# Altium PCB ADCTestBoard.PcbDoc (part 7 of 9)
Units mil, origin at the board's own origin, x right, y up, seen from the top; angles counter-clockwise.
Board outline 11022.62 x 9187 mil, 8 copper layers (TopLayer, InternalPlane1, InternalPlane2, InternalPlane3, InternalPlane4, InternalPlane5, MidLayer1, BottomLayer), stack 103.8 mil thick; 1282 components, 637 nets, 4473 pads, 1306 vias.
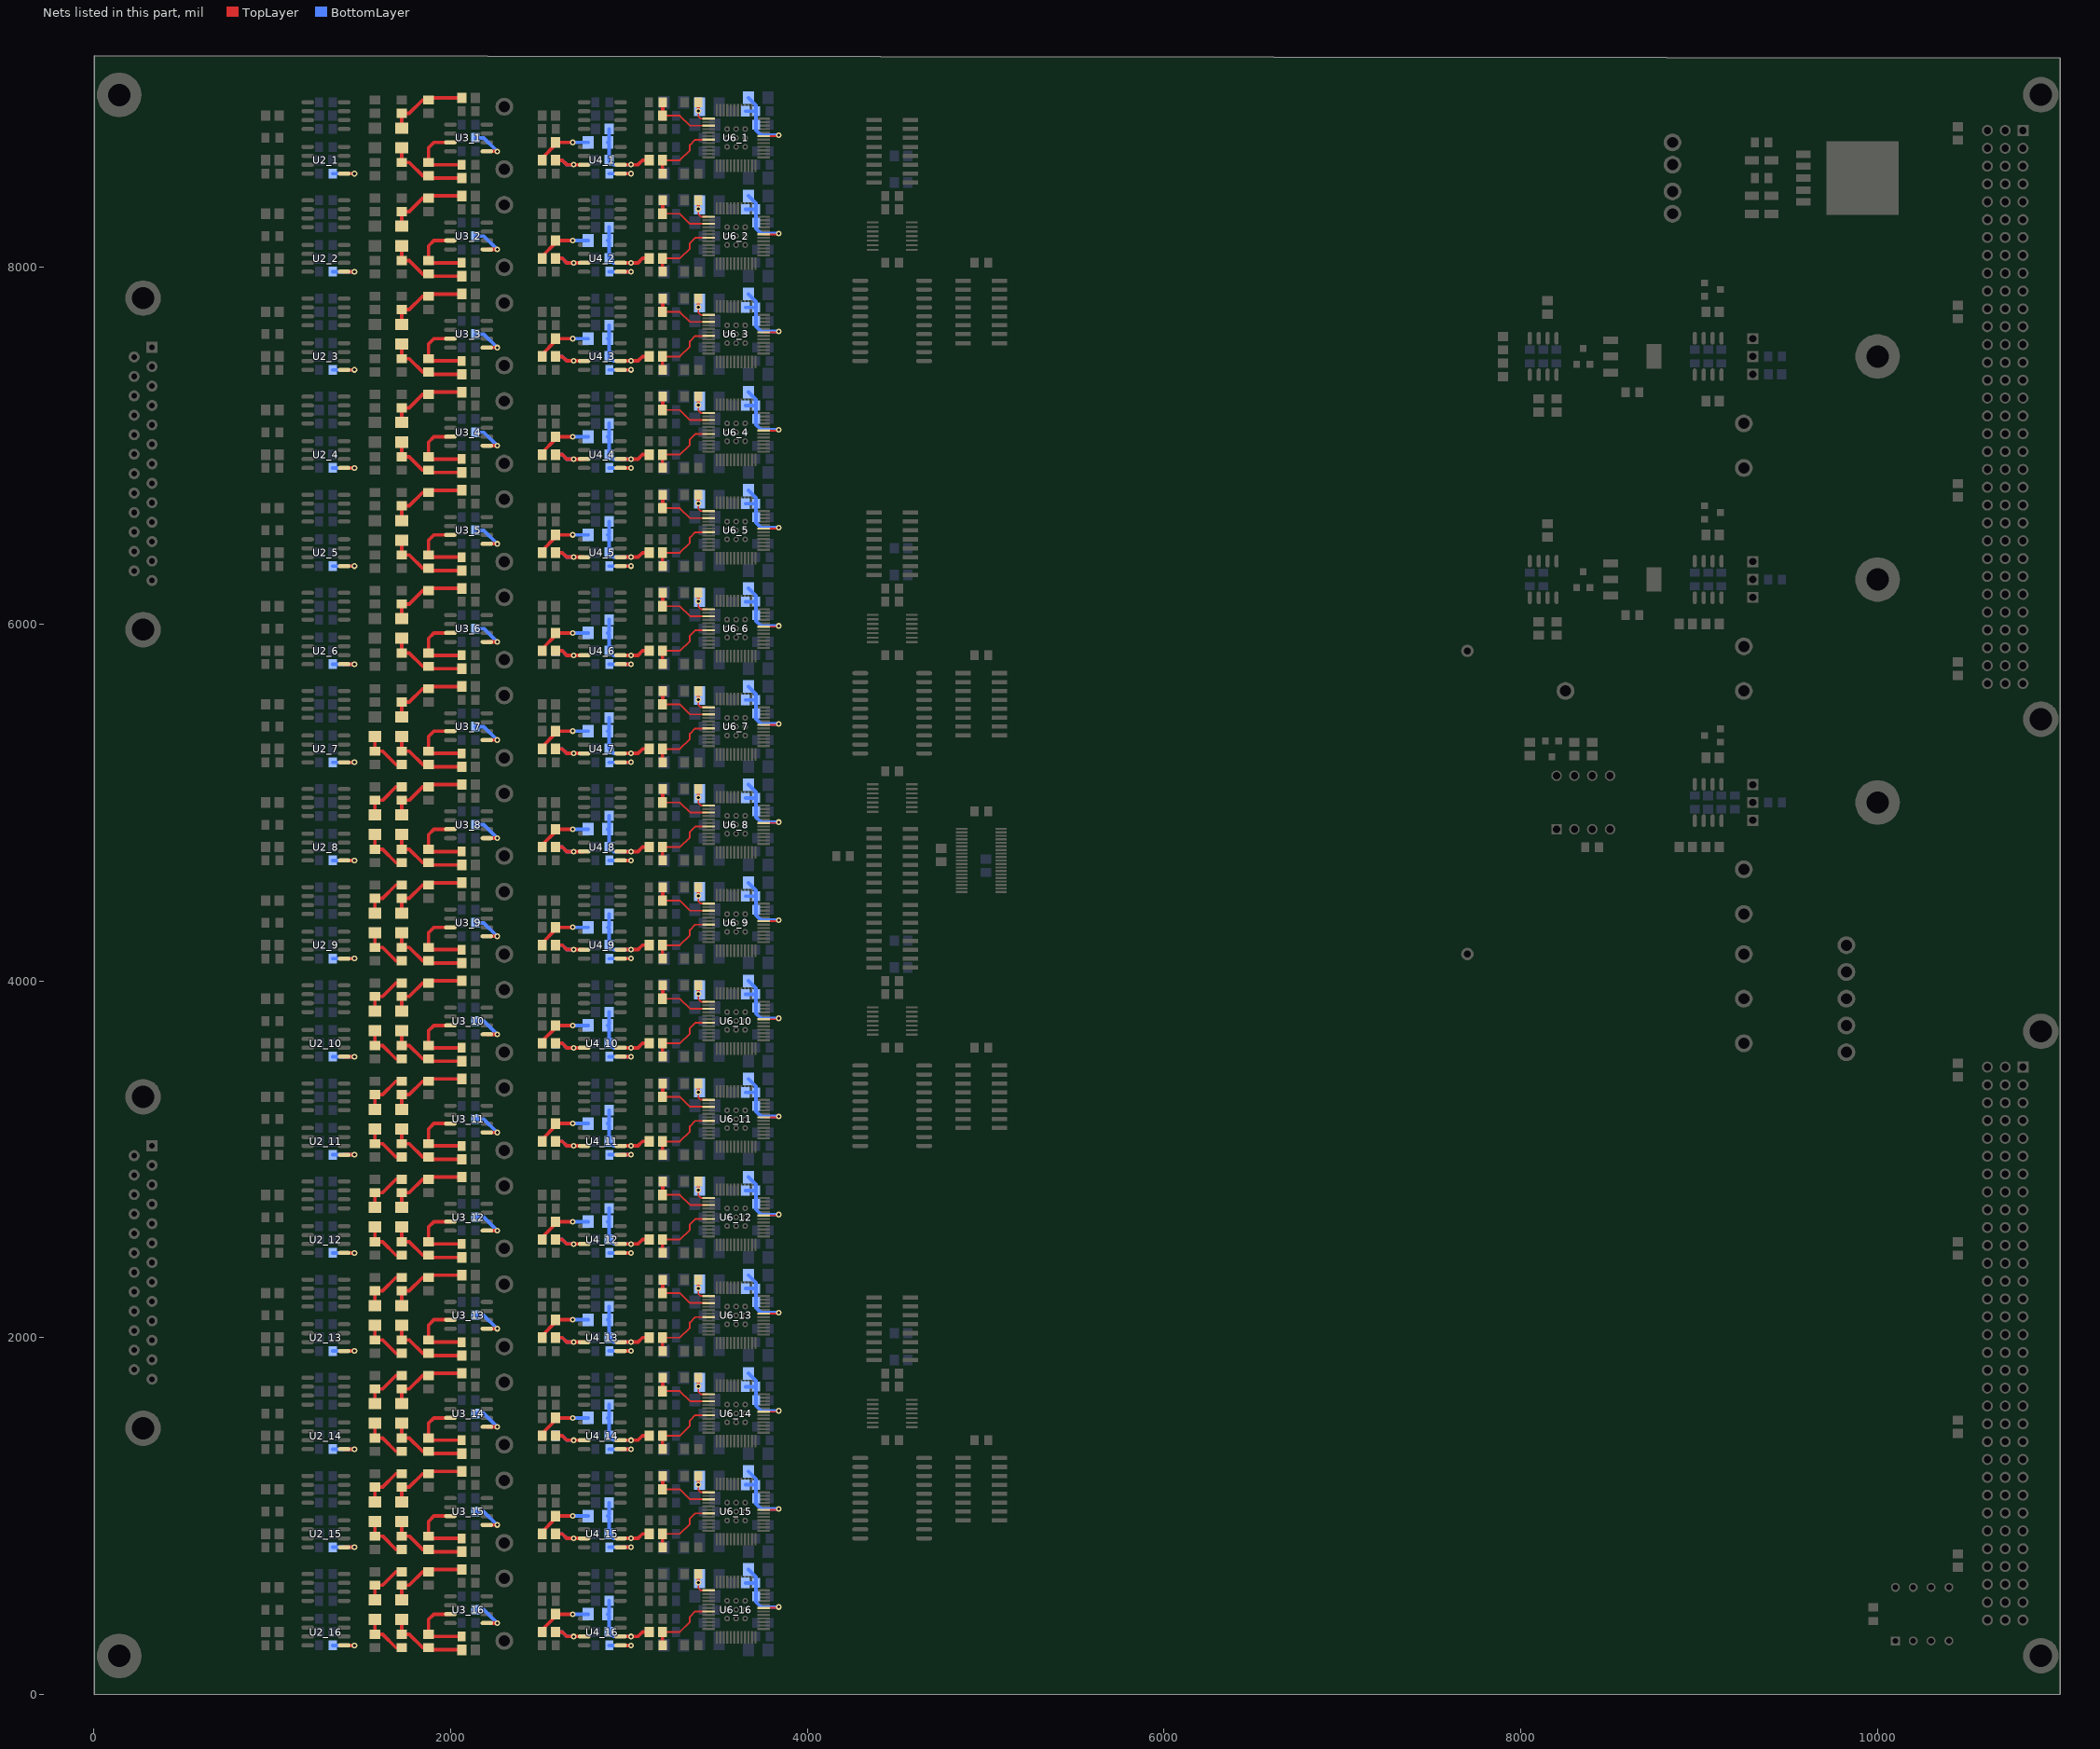
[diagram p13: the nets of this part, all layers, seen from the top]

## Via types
v1: diameter 32, hole 16, TopLayer to BottomLayer, 1306 vias

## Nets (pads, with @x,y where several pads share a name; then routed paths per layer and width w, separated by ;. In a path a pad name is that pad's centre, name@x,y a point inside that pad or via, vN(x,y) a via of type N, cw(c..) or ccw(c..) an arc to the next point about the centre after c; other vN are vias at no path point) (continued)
NetC6_7_2: C6_7.2 R9_7.2 R10_7.1 | length 230.9
  TopLayer w20: C6_7.2@1575,5369.88 R9_7.2@1575,5287.4 1617.6,5287.4 1692.4,5212.6
NetC6_8_1: C6_8.1 R4_8.2 R5_8.1 | length 230.9
  TopLayer w20: C6_8.1@1575,4930.12 R4_8.2@1575,5012.6 1617.6,5012.6 1692.4,5087.4
NetC6_8_2: C6_8.2 R9_8.2 R10_8.1 | length 230.9
  TopLayer w20: C6_8.2@1575,4819.88 R9_8.2@1575,4737.4 1617.6,4737.4 1692.4,4662.6
NetC6_9_1: C6_9.1 R4_9.2 R5_9.1 | length 230.9
  TopLayer w20: C6_9.1@1575,4380.12 R4_9.2@1575,4462.6 1617.6,4462.6 1692.4,4537.4
NetC6_9_2: C6_9.2 R9_9.2 R10_9.1 | length 230.9
  TopLayer w20: C6_9.2@1575,4269.88 R9_9.2@1575,4187.4 1617.6,4187.4 1692.4,4112.6
NetC6_10_1: C6_10.1 R4_10.2 R5_10.1 | length 230.9
  TopLayer w20: C6_10.1@1575,3830.12 R4_10.2@1575,3912.6 1617.6,3912.6 1692.4,3987.4
NetC6_10_2: C6_10.2 R9_10.2 R10_10.1 | length 230.9
  TopLayer w20: C6_10.2@1575,3719.88 R9_10.2@1575,3637.4 1617.6,3637.4 1692.4,3562.6
NetC6_11_1: C6_11.1 R4_11.2 R5_11.1 | length 230.9
  TopLayer w20: C6_11.1@1575,3280.12 R4_11.2@1575,3362.6 1617.6,3362.6 1692.4,3437.4
NetC6_11_2: C6_11.2 R9_11.2 R10_11.1 | length 230.9
  TopLayer w20: C6_11.2@1575,3169.88 R9_11.2@1575,3087.4 1617.6,3087.4 1692.4,3012.6
NetC6_12_1: C6_12.1 R4_12.2 R5_12.1 | length 230.9
  TopLayer w20: C6_12.1@1575,2730.12 R4_12.2@1575,2812.6 1617.6,2812.6 1692.4,2887.4
NetC6_12_2: C6_12.2 R9_12.2 R10_12.1 | length 230.9
  TopLayer w20: C6_12.2@1575,2619.88 R9_12.2@1575,2537.4 1617.6,2537.4 1692.4,2462.6
NetC6_13_1: C6_13.1 R4_13.2 R5_13.1 | length 230.9
  TopLayer w20: C6_13.1@1575,2180.12 R4_13.2@1575,2262.6 1617.6,2262.6 1692.4,2337.4
NetC6_13_2: C6_13.2 R9_13.2 R10_13.1 | length 230.9
  TopLayer w20: C6_13.2@1575,2069.88 R9_13.2@1575,1987.4 1617.6,1987.4 1692.4,1912.6
NetC6_14_1: C6_14.1 R4_14.2 R5_14.1 | length 230.9
  TopLayer w20: C6_14.1@1575,1630.12 R4_14.2@1575,1712.6 1617.6,1712.6 1692.4,1787.4
NetC6_14_2: C6_14.2 R9_14.2 R10_14.1 | length 230.9
  TopLayer w20: C6_14.2@1575,1519.88 R9_14.2@1575,1437.4 1617.6,1437.4 1692.4,1362.6
NetC6_15_1: C6_15.1 R4_15.2 R5_15.1 | length 230.9
  TopLayer w20: C6_15.1@1575,1080.12 R4_15.2@1575,1162.6 1617.6,1162.6 1692.4,1237.4
NetC6_15_2: C6_15.2 R9_15.2 R10_15.1 | length 230.9
  TopLayer w20: C6_15.2@1575,969.88 R9_15.2@1575,887.4 1617.6,887.4 1692.4,812.6
NetC6_16_1: C6_16.1 R4_16.2 R5_16.1 | length 230.9
  TopLayer w20: C6_16.1@1575,530.12 R4_16.2@1575,612.6 1617.6,612.6 1692.4,687.4
NetC6_16_2: C6_16.2 R9_16.2 R10_16.1 | length 230.9
  TopLayer w20: C6_16.2@1575,419.88 R9_16.2@1575,337.4 1617.6,337.4 1692.4,262.6
NetC7_1_1: C7_1.1 R2_1.1 R5_1.2 R6_1.1 | length 456.3
  TopLayer w20: C7_1.1@1725,8780.12 R5_1.2@1725,8862.6 1767.6,8862.6 1842.4,8937.4 R6_1.1@1875,8937.4 1887.6,8950 R2_1.1@2062.6,8950
NetC7_1_2: C7_1.2 R7_1.1 R10_1.2 R12_1.1 | length 456.3
  TopLayer w20: C7_1.2@1725,8669.88 R10_1.2@1725,8587.4 1767.6,8587.4 1842.4,8512.6 R7_1.1@1875,8512.6 1887.6,8500 R12_1.1@2062.6,8500
NetC7_2_1: C7_2.1 R2_2.1 R5_2.2 R6_2.1 | length 456.3
  TopLayer w20: C7_2.1@1725,8230.12 R5_2.2@1725,8312.6 1767.6,8312.6 1842.4,8387.4 R6_2.1@1875,8387.4 1887.6,8400 R2_2.1@2062.6,8400
NetC7_2_2: C7_2.2 R7_2.1 R10_2.2 R12_2.1 | length 456.3
  TopLayer w20: C7_2.2@1725,8119.88 R10_2.2@1725,8037.4 1767.6,8037.4 1842.4,7962.6 R7_2.1@1875,7962.6 1887.6,7950 R12_2.1@2062.6,7950
NetC7_3_1: C7_3.1 R2_3.1 R5_3.2 R6_3.1 | length 456.3
  TopLayer w20: C7_3.1@1725,7680.12 R5_3.2@1725,7762.6 1767.6,7762.6 1842.4,7837.4 R6_3.1@1875,7837.4 1887.6,7850 R2_3.1@2062.6,7850
NetC7_3_2: C7_3.2 R7_3.1 R10_3.2 R12_3.1 | length 456.3
  TopLayer w20: C7_3.2@1725,7569.88 R10_3.2@1725,7487.4 1767.6,7487.4 1842.4,7412.6 R7_3.1@1875,7412.6 1887.6,7400 R12_3.1@2062.6,7400
NetC7_4_1: C7_4.1 R2_4.1 R5_4.2 R6_4.1 | length 456.3
  TopLayer w20: C7_4.1@1725,7130.12 R5_4.2@1725,7212.6 1767.6,7212.6 1842.4,7287.4 R6_4.1@1875,7287.4 1887.6,7300 R2_4.1@2062.6,7300
NetC7_4_2: C7_4.2 R7_4.1 R10_4.2 R12_4.1 | length 456.3
  TopLayer w20: C7_4.2@1725,7019.88 R10_4.2@1725,6937.4 1767.6,6937.4 1842.4,6862.6 R7_4.1@1875,6862.6 1887.6,6850 R12_4.1@2062.6,6850
NetC7_5_1: C7_5.1 R2_5.1 R5_5.2 R6_5.1 | length 456.3
  TopLayer w20: C7_5.1@1725,6580.12 R5_5.2@1725,6662.6 1767.6,6662.6 1842.4,6737.4 R6_5.1@1875,6737.4 1887.6,6750 R2_5.1@2062.6,6750
NetC7_5_2: C7_5.2 R7_5.1 R10_5.2 R12_5.1 | length 456.3
  TopLayer w20: C7_5.2@1725,6469.88 R10_5.2@1725,6387.4 1767.6,6387.4 1842.4,6312.6 R7_5.1@1875,6312.6 1887.6,6300 R12_5.1@2062.6,6300
NetC7_6_1: C7_6.1 R2_6.1 R5_6.2 R6_6.1 | length 456.3
  TopLayer w20: C7_6.1@1725,6030.12 R5_6.2@1725,6112.6 1767.6,6112.6 1842.4,6187.4 R6_6.1@1875,6187.4 1887.6,6200 R2_6.1@2062.6,6200
NetC7_6_2: C7_6.2 R7_6.1 R10_6.2 R12_6.1 | length 456.3
  TopLayer w20: C7_6.2@1725,5919.88 R10_6.2@1725,5837.4 1767.6,5837.4 1842.4,5762.6 R7_6.1@1875,5762.6 1887.6,5750 R12_6.1@2062.6,5750
NetC7_7_1: C7_7.1 R2_7.1 R5_7.2 R6_7.1 | length 456.3
  TopLayer w20: C7_7.1@1725,5480.12 R5_7.2@1725,5562.6 1767.6,5562.6 1842.4,5637.4 R6_7.1@1875,5637.4 1887.6,5650 R2_7.1@2062.6,5650
NetC7_7_2: C7_7.2 R7_7.1 R10_7.2 R12_7.1 | length 456.3
  TopLayer w20: C7_7.2@1725,5369.88 R10_7.2@1725,5287.4 1767.6,5287.4 1842.4,5212.6 R7_7.1@1875,5212.6 1887.6,5200 R12_7.1@2062.6,5200
NetC7_8_1: C7_8.1 R2_8.1 R5_8.2 R6_8.1 | length 456.3
  TopLayer w20: C7_8.1@1725,4930.12 R5_8.2@1725,5012.6 1767.6,5012.6 1842.4,5087.4 R6_8.1@1875,5087.4 1887.6,5100 R2_8.1@2062.6,5100
NetC7_8_2: C7_8.2 R7_8.1 R10_8.2 R12_8.1 | length 456.3
  TopLayer w20: C7_8.2@1725,4819.88 R10_8.2@1725,4737.4 1767.6,4737.4 1842.4,4662.6 R7_8.1@1875,4662.6 1887.6,4650 R12_8.1@2062.6,4650
NetC7_9_1: C7_9.1 R2_9.1 R5_9.2 R6_9.1 | length 456.3
  TopLayer w20: C7_9.1@1725,4380.12 R5_9.2@1725,4462.6 1767.6,4462.6 1842.4,4537.4 R6_9.1@1875,4537.4 1887.6,4550 R2_9.1@2062.6,4550
NetC7_9_2: C7_9.2 R7_9.1 R10_9.2 R12_9.1 | length 456.3
  TopLayer w20: C7_9.2@1725,4269.88 R10_9.2@1725,4187.4 1767.6,4187.4 1842.4,4112.6 R7_9.1@1875,4112.6 1887.6,4100 R12_9.1@2062.6,4100
NetC7_10_1: C7_10.1 R2_10.1 R5_10.2 R6_10.1 | length 456.3
  TopLayer w20: C7_10.1@1725,3830.12 R5_10.2@1725,3912.6 1767.6,3912.6 1842.4,3987.4 R6_10.1@1875,3987.4 1887.6,4000 R2_10.1@2062.6,4000
NetC7_10_2: C7_10.2 R7_10.1 R10_10.2 R12_10.1 | length 456.3
  TopLayer w20: C7_10.2@1725,3719.88 R10_10.2@1725,3637.4 1767.6,3637.4 1842.4,3562.6 R7_10.1@1875,3562.6 1887.6,3550 R12_10.1@2062.6,3550
NetC7_11_1: C7_11.1 R2_11.1 R5_11.2 R6_11.1 | length 456.3
  TopLayer w20: C7_11.1@1725,3280.12 R5_11.2@1725,3362.6 1767.6,3362.6 1842.4,3437.4 R6_11.1@1875,3437.4 1887.6,3450 R2_11.1@2062.6,3450
NetC7_11_2: C7_11.2 R7_11.1 R10_11.2 R12_11.1 | length 456.3
  TopLayer w20: C7_11.2@1725,3169.88 R10_11.2@1725,3087.4 1767.6,3087.4 1842.4,3012.6 R7_11.1@1875,3012.6 1887.6,3000 R12_11.1@2062.6,3000
NetC7_12_1: C7_12.1 R2_12.1 R5_12.2 R6_12.1 | length 456.3
  TopLayer w20: C7_12.1@1725,2730.12 R5_12.2@1725,2812.6 1767.6,2812.6 1842.4,2887.4 R6_12.1@1875,2887.4 1887.6,2900 R2_12.1@2062.6,2900
NetC7_12_2: C7_12.2 R7_12.1 R10_12.2 R12_12.1 | length 456.3
  TopLayer w20: C7_12.2@1725,2619.88 R10_12.2@1725,2537.4 1767.6,2537.4 1842.4,2462.6 R7_12.1@1875,2462.6 1887.6,2450 R12_12.1@2062.6,2450
NetC7_13_1: C7_13.1 R2_13.1 R5_13.2 R6_13.1 | length 456.3
  TopLayer w20: C7_13.1@1725,2180.12 R5_13.2@1725,2262.6 1767.6,2262.6 1842.4,2337.4 R6_13.1@1875,2337.4 1887.6,2350 R2_13.1@2062.6,2350
NetC7_13_2: C7_13.2 R7_13.1 R10_13.2 R12_13.1 | length 456.3
  TopLayer w20: C7_13.2@1725,2069.88 R10_13.2@1725,1987.4 1767.6,1987.4 1842.4,1912.6 R7_13.1@1875,1912.6 1887.6,1900 R12_13.1@2062.6,1900
NetC7_14_1: C7_14.1 R2_14.1 R5_14.2 R6_14.1 | length 456.3
  TopLayer w20: C7_14.1@1725,1630.12 R5_14.2@1725,1712.6 1767.6,1712.6 1842.4,1787.4 R6_14.1@1875,1787.4 1887.6,1800 R2_14.1@2062.6,1800
NetC7_14_2: C7_14.2 R7_14.1 R10_14.2 R12_14.1 | length 456.3
  TopLayer w20: C7_14.2@1725,1519.88 R10_14.2@1725,1437.4 1767.6,1437.4 1842.4,1362.6 R7_14.1@1875,1362.6 1887.6,1350 R12_14.1@2062.6,1350
NetC7_15_1: C7_15.1 R2_15.1 R5_15.2 R6_15.1 | length 456.3
  TopLayer w20: C7_15.1@1725,1080.12 R5_15.2@1725,1162.6 1767.6,1162.6 1842.4,1237.4 R6_15.1@1875,1237.4 1887.6,1250 R2_15.1@2062.6,1250
NetC7_15_2: C7_15.2 R7_15.1 R10_15.2 R12_15.1 | length 456.3
  TopLayer w20: C7_15.2@1725,969.88 R10_15.2@1725,887.4 1767.6,887.4 1842.4,812.6 R7_15.1@1875,812.6 1887.6,800 R12_15.1@2062.6,800
NetC7_16_1: C7_16.1 R2_16.1 R5_16.2 R6_16.1 | length 456.3
  TopLayer w20: C7_16.1@1725,530.12 R5_16.2@1725,612.6 1767.6,612.6 1842.4,687.4 R6_16.1@1875,687.4 1887.6,700 R2_16.1@2062.6,700
NetC7_16_2: C7_16.2 R7_16.1 R10_16.2 R12_16.1 | length 456.3
  TopLayer w20: C7_16.2@1725,419.88 R10_16.2@1725,337.4 1767.6,337.4 1842.4,262.6 R7_16.1@1875,262.6 1887.6,250 R12_16.1@2062.6,250
NetC9_1_1: C9_1.1 U3_1.5 | length 210.3
  TopLayer w20: U3_1.5@2202.36,8650 v1(2260,8650)
  BottomLayer w20: C9_1.1@2138.39,8725 2185,8725 v1(2260,8650)
NetC9_2_1: C9_2.1 U3_2.5 | length 210.3
  TopLayer w20: U3_2.5@2202.36,8100 v1(2260,8100)
  BottomLayer w20: C9_2.1@2138.39,8175 2185,8175 v1(2260,8100)
NetC9_3_1: C9_3.1 U3_3.5 | length 210.3
  TopLayer w20: U3_3.5@2202.36,7550 v1(2260,7550)
  BottomLayer w20: C9_3.1@2138.39,7625 2185,7625 v1(2260,7550)
NetC9_4_1: C9_4.1 U3_4.5 | length 210.3
  TopLayer w20: U3_4.5@2202.36,7000 v1(2260,7000)
  BottomLayer w20: C9_4.1@2138.39,7075 2185,7075 v1(2260,7000)
NetC9_5_1: C9_5.1 U3_5.5 | length 210.3
  TopLayer w20: U3_5.5@2202.36,6450 v1(2260,6450)
  BottomLayer w20: C9_5.1@2138.39,6525 2185,6525 v1(2260,6450)
NetC9_6_1: C9_6.1 U3_6.5 | length 210.3
  TopLayer w20: U3_6.5@2202.36,5900 v1(2260,5900)
  BottomLayer w20: C9_6.1@2138.39,5975 2185,5975 v1(2260,5900)
NetC9_7_1: C9_7.1 U3_7.5 | length 210.3
  TopLayer w20: U3_7.5@2202.36,5350 v1(2260,5350)
  BottomLayer w20: C9_7.1@2138.39,5425 2185,5425 v1(2260,5350)
NetC9_8_1: C9_8.1 U3_8.5 | length 210.3
  TopLayer w20: U3_8.5@2202.36,4800 v1(2260,4800)
  BottomLayer w20: C9_8.1@2138.39,4875 2185,4875 v1(2260,4800)
NetC9_9_1: C9_9.1 U3_9.5 | length 210.3
  TopLayer w20: U3_9.5@2202.36,4250 v1(2260,4250)
  BottomLayer w20: C9_9.1@2138.39,4325 2185,4325 v1(2260,4250)
NetC9_10_1: C9_10.1 U3_10.5 | length 210.3
  TopLayer w20: U3_10.5@2202.36,3700 v1(2260,3700)
  BottomLayer w20: C9_10.1@2138.39,3775 2185,3775 v1(2260,3700)
NetC9_11_1: C9_11.1 U3_11.5 | length 210.3
  TopLayer w20: U3_11.5@2202.36,3150 v1(2260,3150)
  BottomLayer w20: C9_11.1@2138.39,3225 2185,3225 v1(2260,3150)
NetC9_12_1: C9_12.1 U3_12.5 | length 210.3
  TopLayer w20: U3_12.5@2202.36,2600 v1(2260,2600)
  BottomLayer w20: C9_12.1@2138.39,2675 2185,2675 v1(2260,2600)
NetC9_13_1: C9_13.1 U3_13.5 | length 210.3
  TopLayer w20: U3_13.5@2202.36,2050 v1(2260,2050)
  BottomLayer w20: C9_13.1@2138.39,2125 2185,2125 v1(2260,2050)
NetC9_14_1: C9_14.1 U3_14.5 | length 210.3
  TopLayer w20: U3_14.5@2202.36,1500 v1(2260,1500)
  BottomLayer w20: C9_14.1@2138.39,1575 2185,1575 v1(2260,1500)
NetC9_15_1: C9_15.1 U3_15.5 | length 210.3
  TopLayer w20: U3_15.5@2202.36,950 v1(2260,950)
  BottomLayer w20: C9_15.1@2138.39,1025 2185,1025 v1(2260,950)
NetC9_16_1: C9_16.1 U3_16.5 | length 210.3
  TopLayer w20: U3_16.5@2202.36,400 v1(2260,400)
  BottomLayer w20: C9_16.1@2138.39,475 2185,475 v1(2260,400)
NetC11_1_1: C11_1.1 U2_1.5 | length 179.3
  TopLayer w20: U2_1.5@1402.36,8525 v1(1460,8525)
  BottomLayer w20: C11_1.1@1338.39,8525 v1(1460,8525)
NetC11_2_1: C11_2.1 U2_2.5 | length 179.3
  TopLayer w20: U2_2.5@1402.36,7975 v1(1460,7975)
  BottomLayer w20: C11_2.1@1338.39,7975 v1(1460,7975)
NetC11_3_1: C11_3.1 U2_3.5 | length 179.3
  TopLayer w20: U2_3.5@1402.36,7425 v1(1460,7425)
  BottomLayer w20: C11_3.1@1338.39,7425 v1(1460,7425)
NetC11_4_1: C11_4.1 U2_4.5 | length 179.3
  TopLayer w20: U2_4.5@1402.36,6875 v1(1460,6875)
  BottomLayer w20: C11_4.1@1338.39,6875 v1(1460,6875)
NetC11_5_1: C11_5.1 U2_5.5 | length 179.3
  TopLayer w20: U2_5.5@1402.36,6325 v1(1460,6325)
  BottomLayer w20: C11_5.1@1338.39,6325 v1(1460,6325)
NetC11_6_1: C11_6.1 U2_6.5 | length 179.3
  TopLayer w20: U2_6.5@1402.36,5775 v1(1460,5775)
  BottomLayer w20: C11_6.1@1338.39,5775 v1(1460,5775)
NetC11_7_1: C11_7.1 U2_7.5 | length 179.3
  TopLayer w20: U2_7.5@1402.36,5225 v1(1460,5225)
  BottomLayer w20: C11_7.1@1338.39,5225 v1(1460,5225)
NetC11_8_1: C11_8.1 U2_8.5 | length 179.3
  TopLayer w20: U2_8.5@1402.36,4675 v1(1460,4675)
  BottomLayer w20: C11_8.1@1338.39,4675 v1(1460,4675)
NetC11_9_1: C11_9.1 U2_9.5 | length 179.3
  TopLayer w20: U2_9.5@1402.36,4125 v1(1460,4125)
  BottomLayer w20: C11_9.1@1338.39,4125 v1(1460,4125)
NetC11_10_1: C11_10.1 U2_10.5 | length 179.3
  TopLayer w20: U2_10.5@1402.36,3575 v1(1460,3575)
  BottomLayer w20: C11_10.1@1338.39,3575 v1(1460,3575)
NetC11_11_1: C11_11.1 U2_11.5 | length 179.3
  TopLayer w20: U2_11.5@1402.36,3025 v1(1460,3025)
  BottomLayer w20: C11_11.1@1338.39,3025 v1(1460,3025)
NetC11_12_1: C11_12.1 U2_12.5 | length 179.3
  TopLayer w20: U2_12.5@1402.36,2475 v1(1460,2475)
  BottomLayer w20: C11_12.1@1338.39,2475 v1(1460,2475)
NetC11_13_1: C11_13.1 U2_13.5 | length 179.3
  TopLayer w20: U2_13.5@1402.36,1925 v1(1460,1925)
  BottomLayer w20: C11_13.1@1338.39,1925 v1(1460,1925)
NetC11_14_1: C11_14.1 U2_14.5 | length 179.3
  TopLayer w20: U2_14.5@1402.36,1375 v1(1460,1375)
  BottomLayer w20: C11_14.1@1338.39,1375 v1(1460,1375)
NetC11_15_1: C11_15.1 U2_15.5 | length 179.3
  TopLayer w20: U2_15.5@1402.36,825 v1(1460,825)
  BottomLayer w20: C11_15.1@1338.39,825 v1(1460,825)
NetC11_16_1: C11_16.1 U2_16.5 | length 179.3
  TopLayer w20: U2_16.5@1402.36,275 v1(1460,275)
  BottomLayer w20: C11_16.1@1338.39,275 v1(1460,275)
NetC12_1_2: C12_1.2 R7_1.2 U3_1.3 | length 409.4
  TopLayer w20: U3_1.3@1997.64,8700 1905,8700 1875,8670 R7_1.2@1875,8587.4 1887.4,8575 C12_1.2@2061.61,8575
NetC12_2_2: C12_2.2 R7_2.2 U3_2.3 | length 409.4
  TopLayer w20: U3_2.3@1997.64,8150 1905,8150 1875,8120 R7_2.2@1875,8037.4 1887.4,8025 C12_2.2@2061.61,8025
NetC12_3_2: C12_3.2 R7_3.2 U3_3.3 | length 409.4
  TopLayer w20: U3_3.3@1997.64,7600 1905,7600 1875,7570 R7_3.2@1875,7487.4 1887.4,7475 C12_3.2@2061.61,7475
NetC12_4_2: C12_4.2 R7_4.2 U3_4.3 | length 409.4
  TopLayer w20: U3_4.3@1997.64,7050 1905,7050 1875,7020 R7_4.2@1875,6937.4 1887.4,6925 C12_4.2@2061.61,6925
NetC12_5_2: C12_5.2 R7_5.2 U3_5.3 | length 409.4
  TopLayer w20: U3_5.3@1997.64,6500 1905,6500 1875,6470 R7_5.2@1875,6387.4 1887.4,6375 C12_5.2@2061.61,6375
NetC12_6_2: C12_6.2 R7_6.2 U3_6.3 | length 409.4
  TopLayer w20: U3_6.3@1997.64,5950 1905,5950 1875,5920 R7_6.2@1875,5837.4 1887.4,5825 C12_6.2@2061.61,5825
NetC12_7_2: C12_7.2 R7_7.2 U3_7.3 | length 409.4
  TopLayer w20: U3_7.3@1997.64,5400 1905,5400 1875,5370 R7_7.2@1875,5287.4 1887.4,5275 C12_7.2@2061.61,5275
NetC12_8_2: C12_8.2 R7_8.2 U3_8.3 | length 409.4
  TopLayer w20: U3_8.3@1997.64,4850 1905,4850 1875,4820 R7_8.2@1875,4737.4 1887.4,4725 C12_8.2@2061.61,4725
NetC12_9_2: C12_9.2 R7_9.2 U3_9.3 | length 409.4
  TopLayer w20: U3_9.3@1997.64,4300 1905,4300 1875,4270 R7_9.2@1875,4187.4 1887.4,4175 C12_9.2@2061.61,4175
NetC12_10_2: C12_10.2 R7_10.2 U3_10.3 | length 409.4
  TopLayer w20: U3_10.3@1997.64,3750 1905,3750 1875,3720 R7_10.2@1875,3637.4 1887.4,3625 C12_10.2@2061.61,3625
NetC12_11_2: C12_11.2 R7_11.2 U3_11.3 | length 409.4
  TopLayer w20: U3_11.3@1997.64,3200 1905,3200 1875,3170 R7_11.2@1875,3087.4 1887.4,3075 C12_11.2@2061.61,3075
NetC12_12_2: C12_12.2 R7_12.2 U3_12.3 | length 409.4
  TopLayer w20: U3_12.3@1997.64,2650 1905,2650 1875,2620 R7_12.2@1875,2537.4 1887.4,2525 C12_12.2@2061.61,2525
NetC12_13_2: C12_13.2 R7_13.2 U3_13.3 | length 409.4
  TopLayer w20: U3_13.3@1997.64,2100 1905,2100 1875,2070 R7_13.2@1875,1987.4 1887.4,1975 C12_13.2@2061.61,1975
NetC12_14_2: C12_14.2 R7_14.2 U3_14.3 | length 409.4
  TopLayer w20: U3_14.3@1997.64,1550 1905,1550 1875,1520 R7_14.2@1875,1437.4 1887.4,1425 C12_14.2@2061.61,1425
NetC12_15_2: C12_15.2 R7_15.2 U3_15.3 | length 409.4
  TopLayer w20: U3_15.3@1997.64,1000 1905,1000 1875,970 R7_15.2@1875,887.4 1887.4,875 C12_15.2@2061.61,875
NetC12_16_2: C12_16.2 R7_16.2 U3_16.3 | length 409.4
  TopLayer w20: U3_16.3@1997.64,450 1905,450 1875,420 R7_16.2@1875,337.4 1887.4,325 C12_16.2@2061.61,325
NetC16_1_2: C16_1.2 C17_1.2 C18_1.2 R8_1.1 U6_1.19 | length 485.4
  TopLayer w10: U6_1.19@3755,8734.84 3834.84,8734.84 v1(3840,8740)
  BottomLayer w20: R8_1.1@3652.4,8875 C17_1.2@3711.61,8875 ; C18_1.2@3669.88,8950 3711.61,8908.27 3711.61,8768.39 3740,8740 v1(3840,8740)
NetC16_2_2: C16_2.2 C17_2.2 C18_2.2 R8_2.1 U6_2.19 | length 485.4
  TopLayer w10: U6_2.19@3755,8184.84 3834.84,8184.84 v1(3840,8190)
  BottomLayer w20: R8_2.1@3652.4,8325 C17_2.2@3711.61,8325 ; C18_2.2@3669.88,8400 3711.61,8358.27 3711.61,8218.39 3740,8190 v1(3840,8190)
NetC16_3_2: C16_3.2 C17_3.2 C18_3.2 R8_3.1 U6_3.19 | length 485.4
  TopLayer w10: U6_3.19@3755,7634.84 3834.84,7634.84 v1(3840,7640)
  BottomLayer w20: R8_3.1@3652.4,7775 C17_3.2@3711.61,7775 ; C18_3.2@3669.88,7850 3711.61,7808.27 3711.61,7668.39 3740,7640 v1(3840,7640)
NetC16_4_2: C16_4.2 C17_4.2 C18_4.2 R8_4.1 U6_4.19 | length 485.4
  TopLayer w10: U6_4.19@3755,7084.84 3834.84,7084.84 v1(3840,7090)
  BottomLayer w20: R8_4.1@3652.4,7225 C17_4.2@3711.61,7225 ; C18_4.2@3669.88,7300 3711.61,7258.27 3711.61,7118.39 3740,7090 v1(3840,7090)
NetC16_5_2: C16_5.2 C17_5.2 C18_5.2 R8_5.1 U6_5.19 | length 485.4
  TopLayer w10: U6_5.19@3755,6534.84 3834.84,6534.84 v1(3840,6540)
  BottomLayer w20: R8_5.1@3652.4,6675 C17_5.2@3711.61,6675 ; C18_5.2@3669.88,6750 3711.61,6708.27 3711.61,6568.39 3740,6540 v1(3840,6540)
NetC16_6_2: C16_6.2 C17_6.2 C18_6.2 R8_6.1 U6_6.19 | length 485.4
  TopLayer w10: U6_6.19@3755,5984.84 3834.84,5984.84 v1(3840,5990)
  BottomLayer w20: R8_6.1@3652.4,6125 C17_6.2@3711.61,6125 ; C18_6.2@3669.88,6200 3711.61,6158.27 3711.61,6018.39 3740,5990 v1(3840,5990)
NetC16_7_2: C16_7.2 C17_7.2 C18_7.2 R8_7.1 U6_7.19 | length 485.4
  TopLayer w10: U6_7.19@3755,5434.84 3834.84,5434.84 v1(3840,5440)
  BottomLayer w20: R8_7.1@3652.4,5575 C17_7.2@3711.61,5575 ; C18_7.2@3669.88,5650 3711.61,5608.27 3711.61,5468.39 3740,5440 v1(3840,5440)
NetC16_8_2: C16_8.2 C17_8.2 C18_8.2 R8_8.1 U6_8.19 | length 485.4
  TopLayer w10: U6_8.19@3755,4884.84 3834.84,4884.84 v1(3840,4890)
  BottomLayer w20: R8_8.1@3652.4,5025 C17_8.2@3711.61,5025 ; C18_8.2@3669.88,5100 3711.61,5058.27 3711.61,4918.39 3740,4890 v1(3840,4890)
NetC16_9_2: C16_9.2 C17_9.2 C18_9.2 R8_9.1 U6_9.19 | length 485.4
  TopLayer w10: U6_9.19@3755,4334.84 3834.84,4334.84 v1(3840,4340)
  BottomLayer w20: R8_9.1@3652.4,4475 C17_9.2@3711.61,4475 ; C18_9.2@3669.88,4550 3711.61,4508.27 3711.61,4368.39 3740,4340 v1(3840,4340)
NetC16_10_2: C16_10.2 C17_10.2 C18_10.2 R8_10.1 U6_10.19 | length 485.4
  TopLayer w10: U6_10.19@3755,3784.84 3834.84,3784.84 v1(3840,3790)
  BottomLayer w20: R8_10.1@3652.4,3925 C17_10.2@3711.61,3925 ; C18_10.2@3669.88,4000 3711.61,3958.27 3711.61,3818.39 3740,3790 v1(3840,3790)
NetC16_11_2: C16_11.2 C17_11.2 C18_11.2 R8_11.1 U6_11.19 | length 485.4
  TopLayer w10: U6_11.19@3755,3234.84 3834.84,3234.84 v1(3840,3240)
  BottomLayer w20: R8_11.1@3652.4,3375 C17_11.2@3711.61,3375 ; C18_11.2@3669.88,3450 3711.61,3408.27 3711.61,3268.39 3740,3240 v1(3840,3240)
NetC16_12_2: C16_12.2 C17_12.2 C18_12.2 R8_12.1 U6_12.19 | length 485.4
  TopLayer w10: U6_12.19@3755,2684.84 3834.84,2684.84 v1(3840,2690)
  BottomLayer w20: R8_12.1@3652.4,2825 C17_12.2@3711.61,2825 ; C18_12.2@3669.88,2900 3711.61,2858.27 3711.61,2718.39 3740,2690 v1(3840,2690)
NetC16_13_2: C16_13.2 C17_13.2 C18_13.2 R8_13.1 U6_13.19 | length 485.4
  TopLayer w10: U6_13.19@3755,2134.84 3834.84,2134.84 v1(3840,2140)
  BottomLayer w20: R8_13.1@3652.4,2275 C17_13.2@3711.61,2275 ; C18_13.2@3669.88,2350 3711.61,2308.27 3711.61,2168.39 3740,2140 v1(3840,2140)
NetC16_14_2: C16_14.2 C17_14.2 C18_14.2 R8_14.1 U6_14.19 | length 485.4
  TopLayer w10: U6_14.19@3755,1584.84 3834.84,1584.84 v1(3840,1590)
  BottomLayer w20: R8_14.1@3652.4,1725 C17_14.2@3711.61,1725 ; C18_14.2@3669.88,1800 3711.61,1758.27 3711.61,1618.39 3740,1590 v1(3840,1590)
NetC16_15_2: C16_15.2 C17_15.2 C18_15.2 R8_15.1 U6_15.19 | length 485.4
  TopLayer w10: U6_15.19@3755,1034.84 3834.84,1034.84 v1(3840,1040)
  BottomLayer w20: R8_15.1@3652.4,1175 C17_15.2@3711.61,1175 ; C18_15.2@3669.88,1250 3711.61,1208.27 3711.61,1068.39 3740,1040 v1(3840,1040)
NetC16_16_2: C16_16.2 C17_16.2 C18_16.2 R8_16.1 U6_16.19 | length 485.4
  TopLayer w10: U6_16.19@3755,484.84 3834.84,484.84 v1(3840,490)
  BottomLayer w20: R8_16.1@3652.4,625 C17_16.2@3711.61,625 ; C18_16.2@3669.88,700 3711.61,658.27 3711.61,518.39 3740,490 v1(3840,490)
NetC26_1_1: C26_1.1 R14_1.1 U6_1.43 | length 388.9
  TopLayer w10: R14_1.1@3187.4,8600 3285,8600 3340,8655 3340,8685 3370.16,8715.16 U6_1.43@3435.63,8715.16
  TopLayer w20: R14_1.1@3187.4,8600 3187.4,8525.98 C26_1.1@3188.39,8525
NetC26_2_1: C26_2.1 R14_2.1 U6_2.43 | length 388.9
  TopLayer w10: R14_2.1@3187.4,8050 3285,8050 3340,8105 3340,8135 3370.16,8165.16 U6_2.43@3435.63,8165.16
  TopLayer w20: R14_2.1@3187.4,8050 3187.4,7975.98 C26_2.1@3188.39,7975
NetC26_3_1: C26_3.1 R14_3.1 U6_3.43 | length 388.9
  TopLayer w10: R14_3.1@3187.4,7500 3285,7500 3340,7555 3340,7585 3370.16,7615.16 U6_3.43@3435.63,7615.16
  TopLayer w20: R14_3.1@3187.4,7500 3187.4,7425.98 C26_3.1@3188.39,7425
NetC26_4_1: C26_4.1 R14_4.1 U6_4.43 | length 388.9
  TopLayer w10: R14_4.1@3187.4,6950 3285,6950 3340,7005 3340,7035 3370.16,7065.16 U6_4.43@3435.63,7065.16
  TopLayer w20: R14_4.1@3187.4,6950 3187.4,6875.98 C26_4.1@3188.39,6875
NetC26_5_1: C26_5.1 R14_5.1 U6_5.43 | length 388.9
  TopLayer w10: R14_5.1@3187.4,6400 3285,6400 3340,6455 3340,6485 3370.16,6515.16 U6_5.43@3435.63,6515.16
  TopLayer w20: R14_5.1@3187.4,6400 3187.4,6325.98 C26_5.1@3188.39,6325
NetC26_6_1: C26_6.1 R14_6.1 U6_6.43 | length 388.9
  TopLayer w10: R14_6.1@3187.4,5850 3285,5850 3340,5905 3340,5935 3370.16,5965.16 U6_6.43@3435.63,5965.16
  TopLayer w20: R14_6.1@3187.4,5850 3187.4,5775.98 C26_6.1@3188.39,5775
NetC26_7_1: C26_7.1 R14_7.1 U6_7.43 | length 388.9
  TopLayer w10: R14_7.1@3187.4,5300 3285,5300 3340,5355 3340,5385 3370.16,5415.16 U6_7.43@3435.63,5415.16
  TopLayer w20: R14_7.1@3187.4,5300 3187.4,5225.98 C26_7.1@3188.39,5225
NetC26_8_1: C26_8.1 R14_8.1 U6_8.43 | length 388.9
  TopLayer w10: R14_8.1@3187.4,4750 3285,4750 3340,4805 3340,4835 3370.16,4865.16 U6_8.43@3435.63,4865.16
  TopLayer w20: R14_8.1@3187.4,4750 3187.4,4675.98 C26_8.1@3188.39,4675
NetC26_9_1: C26_9.1 R14_9.1 U6_9.43 | length 388.9
  TopLayer w10: R14_9.1@3187.4,4200 3285,4200 3340,4255 3340,4285 3370.16,4315.16 U6_9.43@3435.63,4315.16
  TopLayer w20: R14_9.1@3187.4,4200 3187.4,4125.98 C26_9.1@3188.39,4125
NetC26_10_1: C26_10.1 R14_10.1 U6_10.43 | length 388.9
  TopLayer w10: R14_10.1@3187.4,3650 3285,3650 3340,3705 3340,3735 3370.16,3765.16 U6_10.43@3435.63,3765.16
  TopLayer w20: R14_10.1@3187.4,3650 3187.4,3575.98 C26_10.1@3188.39,3575
NetC26_11_1: C26_11.1 R14_11.1 U6_11.43 | length 388.9
  TopLayer w10: R14_11.1@3187.4,3100 3285,3100 3340,3155 3340,3185 3370.16,3215.16 U6_11.43@3435.63,3215.16
  TopLayer w20: R14_11.1@3187.4,3100 3187.4,3025.98 C26_11.1@3188.39,3025
NetC26_12_1: C26_12.1 R14_12.1 U6_12.43 | length 388.9
  TopLayer w10: R14_12.1@3187.4,2550 3285,2550 3340,2605 3340,2635 3370.16,2665.16 U6_12.43@3435.63,2665.16
  TopLayer w20: R14_12.1@3187.4,2550 3187.4,2475.98 C26_12.1@3188.39,2475
NetC26_13_1: C26_13.1 R14_13.1 U6_13.43 | length 388.9
  TopLayer w10: R14_13.1@3187.4,2000 3285,2000 3340,2055 3340,2085 3370.16,2115.16 U6_13.43@3435.63,2115.16
  TopLayer w20: R14_13.1@3187.4,2000 3187.4,1925.98 C26_13.1@3188.39,1925
NetC26_14_1: C26_14.1 R14_14.1 U6_14.43 | length 388.9
  TopLayer w10: R14_14.1@3187.4,1450 3285,1450 3340,1505 3340,1535 3370.16,1565.16 U6_14.43@3435.63,1565.16
  TopLayer w20: R14_14.1@3187.4,1450 3187.4,1375.98 C26_14.1@3188.39,1375
NetC26_15_1: C26_15.1 R14_15.1 U6_15.43 | length 388.9
  TopLayer w10: R14_15.1@3187.4,900 3285,900 3340,955 3340,985 3370.16,1015.16 U6_15.43@3435.63,1015.16
  TopLayer w20: R14_15.1@3187.4,900 3187.4,825.98 C26_15.1@3188.39,825
NetC26_16_1: C26_16.1 R14_16.1 U6_16.43 | length 388.9
  TopLayer w10: R14_16.1@3187.4,350 3285,350 3340,405 3340,435 3370.16,465.16 U6_16.43@3435.63,465.16
  TopLayer w20: R14_16.1@3187.4,350 3187.4,275.98 C26_16.1@3188.39,275
NetC27_1_1: C27_1.1 R14_1.2 R16_1.2 R21_1.2 U4_1.6 | length 484.6
  TopLayer w20: U4_1.6@2952.36,8575 3050,8575 3075,8600 R14_1.2@3112.6,8600
  BottomLayer w20: R16_1.2@2887.4,8775 2887.4,8707.28 C27_1.1@2880.12,8700 2887.4,8692.72 R21_1.2@2887.4,8600 2912.4,8575 v1(3010,8575)
NetC27_1_2: C27_1.2 R17_1.2 R18_1.1 | length 313.5
  TopLayer w20: R18_1.1@2512.6,8600 2512.6,8612.6 2587.4,8687.4 R17_1.2@2587.4,8700 v1(2685,8700)
  BottomLayer w20: v1(2685,8700) C27_1.2@2769.88,8700
NetC27_2_1: C27_2.1 R14_2.2 R16_2.2 R21_2.2 U4_2.6 | length 484.6
  TopLayer w20: U4_2.6@2952.36,8025 3050,8025 3075,8050 R14_2.2@3112.6,8050
  BottomLayer w20: R16_2.2@2887.4,8225 2887.4,8157.28 C27_2.1@2880.12,8150 2887.4,8142.72 R21_2.2@2887.4,8050 2912.4,8025 v1(3010,8025)
NetC27_2_2: C27_2.2 R17_2.2 R18_2.1 | length 313.5
  TopLayer w20: R18_2.1@2512.6,8050 2512.6,8062.6 2587.4,8137.4 R17_2.2@2587.4,8150 v1(2685,8150)
  BottomLayer w20: v1(2685,8150) C27_2.2@2769.88,8150
NetC27_3_1: C27_3.1 R14_3.2 R16_3.2 R21_3.2 U4_3.6 | length 484.6
  TopLayer w20: U4_3.6@2952.36,7475 3050,7475 3075,7500 R14_3.2@3112.6,7500
  BottomLayer w20: R16_3.2@2887.4,7675 2887.4,7607.28 C27_3.1@2880.12,7600 2887.4,7592.72 R21_3.2@2887.4,7500 2912.4,7475 v1(3010,7475)
NetC27_3_2: C27_3.2 R17_3.2 R18_3.1 | length 313.5
  TopLayer w20: R18_3.1@2512.6,7500 2512.6,7512.6 2587.4,7587.4 R17_3.2@2587.4,7600 v1(2685,7600)
  BottomLayer w20: v1(2685,7600) C27_3.2@2769.88,7600
NetC27_4_1: C27_4.1 R14_4.2 R16_4.2 R21_4.2 U4_4.6 | length 484.6
  TopLayer w20: U4_4.6@2952.36,6925 3050,6925 3075,6950 R14_4.2@3112.6,6950
  BottomLayer w20: R16_4.2@2887.4,7125 2887.4,7057.28 C27_4.1@2880.12,7050 2887.4,7042.72 R21_4.2@2887.4,6950 2912.4,6925 v1(3010,6925)
NetC27_4_2: C27_4.2 R17_4.2 R18_4.1 | length 313.5
  TopLayer w20: R18_4.1@2512.6,6950 2512.6,6962.6 2587.4,7037.4 R17_4.2@2587.4,7050 v1(2685,7050)
  BottomLayer w20: v1(2685,7050) C27_4.2@2769.88,7050
NetC27_5_1: C27_5.1 R14_5.2 R16_5.2 R21_5.2 U4_5.6 | length 484.6
  TopLayer w20: U4_5.6@2952.36,6375 3050,6375 3075,6400 R14_5.2@3112.6,6400
  BottomLayer w20: R16_5.2@2887.4,6575 2887.4,6507.28 C27_5.1@2880.12,6500 2887.4,6492.72 R21_5.2@2887.4,6400 2912.4,6375 v1(3010,6375)
NetC27_5_2: C27_5.2 R17_5.2 R18_5.1 | length 313.5
  TopLayer w20: R18_5.1@2512.6,6400 2512.6,6412.6 2587.4,6487.4 R17_5.2@2587.4,6500 v1(2685,6500)
  BottomLayer w20: v1(2685,6500) C27_5.2@2769.88,6500
NetC27_6_1: C27_6.1 R14_6.2 R16_6.2 R21_6.2 U4_6.6 | length 484.6
  TopLayer w20: U4_6.6@2952.36,5825 3050,5825 3075,5850 R14_6.2@3112.6,5850
  BottomLayer w20: R16_6.2@2887.4,6025 2887.4,5957.28 C27_6.1@2880.12,5950 2887.4,5942.72 R21_6.2@2887.4,5850 2912.4,5825 v1(3010,5825)
NetC27_6_2: C27_6.2 R17_6.2 R18_6.1 | length 313.5
  TopLayer w20: R18_6.1@2512.6,5850 2512.6,5862.6 2587.4,5937.4 R17_6.2@2587.4,5950 v1(2685,5950)
  BottomLayer w20: v1(2685,5950) C27_6.2@2769.88,5950
NetC27_7_1: C27_7.1 R14_7.2 R16_7.2 R21_7.2 U4_7.6 | length 484.6
  TopLayer w20: U4_7.6@2952.36,5275 3050,5275 3075,5300 R14_7.2@3112.6,5300
  BottomLayer w20: R16_7.2@2887.4,5475 2887.4,5407.28 C27_7.1@2880.12,5400 2887.4,5392.72 R21_7.2@2887.4,5300 2912.4,5275 v1(3010,5275)
NetC27_7_2: C27_7.2 R17_7.2 R18_7.1 | length 313.5
  TopLayer w20: R18_7.1@2512.6,5300 2512.6,5312.6 2587.4,5387.4 R17_7.2@2587.4,5400 v1(2685,5400)
  BottomLayer w20: v1(2685,5400) C27_7.2@2769.88,5400
NetC27_8_1: C27_8.1 R14_8.2 R16_8.2 R21_8.2 U4_8.6 | length 484.6
  TopLayer w20: U4_8.6@2952.36,4725 3050,4725 3075,4750 R14_8.2@3112.6,4750
  BottomLayer w20: R16_8.2@2887.4,4925 2887.4,4857.28 C27_8.1@2880.12,4850 2887.4,4842.72 R21_8.2@2887.4,4750 2912.4,4725 v1(3010,4725)
NetC27_8_2: C27_8.2 R17_8.2 R18_8.1 | length 313.5
  TopLayer w20: R18_8.1@2512.6,4750 2512.6,4762.6 2587.4,4837.4 R17_8.2@2587.4,4850 v1(2685,4850)
  BottomLayer w20: v1(2685,4850) C27_8.2@2769.88,4850
NetC27_9_1: C27_9.1 R14_9.2 R16_9.2 R21_9.2 U4_9.6 | length 484.6
  TopLayer w20: U4_9.6@2952.36,4175 3050,4175 3075,4200 R14_9.2@3112.6,4200
  BottomLayer w20: R16_9.2@2887.4,4375 2887.4,4307.28 C27_9.1@2880.12,4300 2887.4,4292.72 R21_9.2@2887.4,4200 2912.4,4175 v1(3010,4175)
NetC27_9_2: C27_9.2 R17_9.2 R18_9.1 | length 313.5
  TopLayer w20: R18_9.1@2512.6,4200 2512.6,4212.6 2587.4,4287.4 R17_9.2@2587.4,4300 v1(2685,4300)
  BottomLayer w20: v1(2685,4300) C27_9.2@2769.88,4300
NetC27_10_1: C27_10.1 R14_10.2 R16_10.2 R21_10.2 U4_10.6 | length 484.6
  TopLayer w20: U4_10.6@2952.36,3625 3050,3625 3075,3650 R14_10.2@3112.6,3650
  BottomLayer w20: R16_10.2@2887.4,3825 2887.4,3757.28 C27_10.1@2880.12,3750 2887.4,3742.72 R21_10.2@2887.4,3650 2912.4,3625 v1(3010,3625)
NetC27_10_2: C27_10.2 R17_10.2 R18_10.1 | length 313.5
  TopLayer w20: R18_10.1@2512.6,3650 2512.6,3662.6 2587.4,3737.4 R17_10.2@2587.4,3750 v1(2685,3750)
  BottomLayer w20: v1(2685,3750) C27_10.2@2769.88,3750
NetC27_11_1: C27_11.1 R14_11.2 R16_11.2 R21_11.2 U4_11.6 | length 484.6
  TopLayer w20: U4_11.6@2952.36,3075 3050,3075 3075,3100 R14_11.2@3112.6,3100
  BottomLayer w20: R16_11.2@2887.4,3275 2887.4,3207.28 C27_11.1@2880.12,3200 2887.4,3192.72 R21_11.2@2887.4,3100 2912.4,3075 v1(3010,3075)
NetC27_11_2: C27_11.2 R17_11.2 R18_11.1 | length 313.5
  TopLayer w20: R18_11.1@2512.6,3100 2512.6,3112.6 2587.4,3187.4 R17_11.2@2587.4,3200 v1(2685,3200)
  BottomLayer w20: v1(2685,3200) C27_11.2@2769.88,3200
NetC27_12_1: C27_12.1 R14_12.2 R16_12.2 R21_12.2 U4_12.6 | length 484.6
  TopLayer w20: U4_12.6@2952.36,2525 3050,2525 3075,2550 R14_12.2@3112.6,2550
  BottomLayer w20: R16_12.2@2887.4,2725 2887.4,2657.28 C27_12.1@2880.12,2650 2887.4,2642.72 R21_12.2@2887.4,2550 2912.4,2525 v1(3010,2525)
NetC27_12_2: C27_12.2 R17_12.2 R18_12.1 | length 313.5
  TopLayer w20: R18_12.1@2512.6,2550 2512.6,2562.6 2587.4,2637.4 R17_12.2@2587.4,2650 v1(2685,2650)
  BottomLayer w20: v1(2685,2650) C27_12.2@2769.88,2650
NetC27_13_1: C27_13.1 R14_13.2 R16_13.2 R21_13.2 U4_13.6 | length 484.6
  TopLayer w20: U4_13.6@2952.36,1975 3050,1975 3075,2000 R14_13.2@3112.6,2000
  BottomLayer w20: R16_13.2@2887.4,2175 2887.4,2107.28 C27_13.1@2880.12,2100 2887.4,2092.72 R21_13.2@2887.4,2000 2912.4,1975 v1(3010,1975)
NetC27_13_2: C27_13.2 R17_13.2 R18_13.1 | length 313.5
  TopLayer w20: R18_13.1@2512.6,2000 2512.6,2012.6 2587.4,2087.4 R17_13.2@2587.4,2100 v1(2685,2100)
  BottomLayer w20: v1(2685,2100) C27_13.2@2769.88,2100
NetC27_14_1: C27_14.1 R14_14.2 R16_14.2 R21_14.2 U4_14.6 | length 484.6
  TopLayer w20: U4_14.6@2952.36,1425 3050,1425 3075,1450 R14_14.2@3112.6,1450
  BottomLayer w20: R16_14.2@2887.4,1625 2887.4,1557.28 C27_14.1@2880.12,1550 2887.4,1542.72 R21_14.2@2887.4,1450 2912.4,1425 v1(3010,1425)
NetC27_14_2: C27_14.2 R17_14.2 R18_14.1 | length 313.5
  TopLayer w20: R18_14.1@2512.6,1450 2512.6,1462.6 2587.4,1537.4 R17_14.2@2587.4,1550 v1(2685,1550)
  BottomLayer w20: v1(2685,1550) C27_14.2@2769.88,1550
NetC27_15_1: C27_15.1 R14_15.2 R16_15.2 R21_15.2 U4_15.6 | length 484.6
  TopLayer w20: U4_15.6@2952.36,875 3050,875 3075,900 R14_15.2@3112.6,900
  BottomLayer w20: R16_15.2@2887.4,1075 2887.4,1007.28 C27_15.1@2880.12,1000 2887.4,992.72 R21_15.2@2887.4,900 2912.4,875 v1(3010,875)
NetC27_15_2: C27_15.2 R17_15.2 R18_15.1 | length 313.5
  TopLayer w20: R18_15.1@2512.6,900 2512.6,912.6 2587.4,987.4 R17_15.2@2587.4,1000 v1(2685,1000)
  BottomLayer w20: v1(2685,1000) C27_15.2@2769.88,1000
NetC27_16_1: C27_16.1 R14_16.2 R16_16.2 R21_16.2 U4_16.6 | length 484.6
  TopLayer w20: U4_16.6@2952.36,325 3050,325 3075,350 R14_16.2@3112.6,350
  BottomLayer w20: R16_16.2@2887.4,525 2887.4,457.28 C27_16.1@2880.12,450 2887.4,442.72 R21_16.2@2887.4,350 2912.4,325 v1(3010,325)
NetC27_16_2: C27_16.2 R17_16.2 R18_16.1 | length 313.5
  TopLayer w20: R18_16.1@2512.6,350 2512.6,362.6 2587.4,437.4 R17_16.2@2587.4,450 v1(2685,450)
  BottomLayer w20: v1(2685,450) C27_16.2@2769.88,450
NetC30_1_1: C30_1.1 U4_1.5 | length 179.3
  TopLayer w20: U4_1.5@2952.36,8525 v1(3010,8525)
  BottomLayer w20: C30_1.1@2888.39,8525 v1(3010,8525)
NetC30_2_1: C30_2.1 U4_2.5 | length 179.3
  TopLayer w20: U4_2.5@2952.36,7975 v1(3010,7975)
  BottomLayer w20: C30_2.1@2888.39,7975 v1(3010,7975)
NetC30_3_1: C30_3.1 U4_3.5 | length 179.3
  TopLayer w20: U4_3.5@2952.36,7425 v1(3010,7425)
  BottomLayer w20: C30_3.1@2888.39,7425 v1(3010,7425)
NetC30_4_1: C30_4.1 U4_4.5 | length 179.3
  TopLayer w20: U4_4.5@2952.36,6875 v1(3010,6875)
  BottomLayer w20: C30_4.1@2888.39,6875 v1(3010,6875)
NetC30_5_1: C30_5.1 U4_5.5 | length 179.3
  TopLayer w20: U4_5.5@2952.36,6325 v1(3010,6325)
  BottomLayer w20: C30_5.1@2888.39,6325 v1(3010,6325)
NetC30_6_1: C30_6.1 U4_6.5 | length 179.3
  TopLayer w20: U4_6.5@2952.36,5775 v1(3010,5775)
  BottomLayer w20: C30_6.1@2888.39,5775 v1(3010,5775)
NetC30_7_1: C30_7.1 U4_7.5 | length 179.3
  TopLayer w20: U4_7.5@2952.36,5225 v1(3010,5225)
  BottomLayer w20: C30_7.1@2888.39,5225 v1(3010,5225)
NetC30_8_1: C30_8.1 U4_8.5 | length 179.3
  TopLayer w20: U4_8.5@2952.36,4675 v1(3010,4675)
  BottomLayer w20: C30_8.1@2888.39,4675 v1(3010,4675)
NetC30_9_1: C30_9.1 U4_9.5 | length 179.3
  TopLayer w20: U4_9.5@2952.36,4125 v1(3010,4125)
  BottomLayer w20: C30_9.1@2888.39,4125 v1(3010,4125)
NetC30_10_1: C30_10.1 U4_10.5 | length 179.3
  TopLayer w20: U4_10.5@2952.36,3575 v1(3010,3575)
  BottomLayer w20: C30_10.1@2888.39,3575 v1(3010,3575)
NetC30_11_1: C30_11.1 U4_11.5 | length 179.3
  TopLayer w20: U4_11.5@2952.36,3025 v1(3010,3025)
  BottomLayer w20: C30_11.1@2888.39,3025 v1(3010,3025)
NetC30_12_1: C30_12.1 U4_12.5 | length 179.3
  TopLayer w20: U4_12.5@2952.36,2475 v1(3010,2475)
  BottomLayer w20: C30_12.1@2888.39,2475 v1(3010,2475)
NetC30_13_1: C30_13.1 U4_13.5 | length 179.3
  TopLayer w20: U4_13.5@2952.36,1925 v1(3010,1925)
  BottomLayer w20: C30_13.1@2888.39,1925 v1(3010,1925)
NetC30_14_1: C30_14.1 U4_14.5 | length 179.3
  TopLayer w20: U4_14.5@2952.36,1375 v1(3010,1375)
  BottomLayer w20: C30_14.1@2888.39,1375 v1(3010,1375)
NetC30_15_1: C30_15.1 U4_15.5 | length 179.3
  TopLayer w20: U4_15.5@2952.36,825 v1(3010,825)
  BottomLayer w20: C30_15.1@2888.39,825 v1(3010,825)
NetC30_16_1: C30_16.1 U4_16.5 | length 179.3
  TopLayer w20: U4_16.5@2952.36,275 v1(3010,275)
  BottomLayer w20: C30_16.1@2888.39,275 v1(3010,275)
NetC31_1_1: C31_1.1 C32_1.1 U6_1.37 | length 131.2
  TopLayer w10: v1(3388.39,8876.61) 3388.39,8846.61 3401.73,8833.27 U6_1.37@3435.63,8833.27
  TopLayer w20: v1(3388.39,8876.61) C32_1.1@3388.39,8925
NetC31_2_1: C31_2.1 C32_2.1 U6_2.37 | length 131.2
  TopLayer w10: v1(3388.39,8326.61) 3388.39,8296.61 3401.73,8283.27 U6_2.37@3435.63,8283.27
  TopLayer w20: v1(3388.39,8326.61) C32_2.1@3388.39,8375
NetC31_3_1: C31_3.1 C32_3.1 U6_3.37 | length 131.2
  TopLayer w10: v1(3388.39,7776.61) 3388.39,7746.61 3401.73,7733.27 U6_3.37@3435.63,7733.27
  TopLayer w20: v1(3388.39,7776.61) C32_3.1@3388.39,7825
NetC31_4_1: C31_4.1 C32_4.1 U6_4.37 | length 131.2
  TopLayer w10: v1(3388.39,7226.61) 3388.39,7196.61 3401.73,7183.27 U6_4.37@3435.63,7183.27
  TopLayer w20: v1(3388.39,7226.61) C32_4.1@3388.39,7275
NetC31_5_1: C31_5.1 C32_5.1 U6_5.37 | length 131.2
  TopLayer w10: v1(3388.39,6676.61) 3388.39,6646.61 3401.73,6633.27 U6_5.37@3435.63,6633.27
  TopLayer w20: v1(3388.39,6676.61) C32_5.1@3388.39,6725
NetC31_6_1: C31_6.1 C32_6.1 U6_6.37 | length 131.2
  TopLayer w10: v1(3388.39,6126.61) 3388.39,6096.61 3401.73,6083.27 U6_6.37@3435.63,6083.27
  TopLayer w20: v1(3388.39,6126.61) C32_6.1@3388.39,6175
NetC31_7_1: C31_7.1 C32_7.1 U6_7.37 | length 131.2
  TopLayer w10: v1(3388.39,5576.61) 3388.39,5546.61 3401.73,5533.27 U6_7.37@3435.63,5533.27
  TopLayer w20: v1(3388.39,5576.61) C32_7.1@3388.39,5625
NetC31_8_1: C31_8.1 C32_8.1 U6_8.37 | length 131.2
  TopLayer w10: v1(3388.39,5026.61) 3388.39,4996.61 3401.73,4983.27 U6_8.37@3435.63,4983.27
  TopLayer w20: v1(3388.39,5026.61) C32_8.1@3388.39,5075
NetC31_9_1: C31_9.1 C32_9.1 U6_9.37 | length 131.2
  TopLayer w10: v1(3388.39,4476.61) 3388.39,4446.61 3401.73,4433.27 U6_9.37@3435.63,4433.27
  TopLayer w20: v1(3388.39,4476.61) C32_9.1@3388.39,4525
NetC31_10_1: C31_10.1 C32_10.1 U6_10.37 | length 131.2
  TopLayer w10: v1(3388.39,3926.61) 3388.39,3896.61 3401.73,3883.27 U6_10.37@3435.63,3883.27
  TopLayer w20: v1(3388.39,3926.61) C32_10.1@3388.39,3975
NetC31_11_1: C31_11.1 C32_11.1 U6_11.37 | length 131.2
  TopLayer w10: v1(3388.39,3376.61) 3388.39,3346.61 3401.73,3333.27 U6_11.37@3435.63,3333.27
  TopLayer w20: v1(3388.39,3376.61) C32_11.1@3388.39,3425
NetC31_12_1: C31_12.1 C32_12.1 U6_12.37 | length 131.2
  TopLayer w10: v1(3388.39,2826.61) 3388.39,2796.61 3401.73,2783.27 U6_12.37@3435.63,2783.27
  TopLayer w20: v1(3388.39,2826.61) C32_12.1@3388.39,2875
NetC31_13_1: C31_13.1 C32_13.1 U6_13.37 | length 131.2
  TopLayer w10: v1(3388.39,2276.61) 3388.39,2246.61 3401.73,2233.27 U6_13.37@3435.63,2233.27
  TopLayer w20: v1(3388.39,2276.61) C32_13.1@3388.39,2325
NetC31_14_1: C31_14.1 C32_14.1 U6_14.37 | length 131.2
  TopLayer w10: v1(3388.39,1726.61) 3388.39,1696.61 3401.73,1683.27 U6_14.37@3435.63,1683.27
  TopLayer w20: v1(3388.39,1726.61) C32_14.1@3388.39,1775
NetC31_15_1: C31_15.1 C32_15.1 U6_15.37 | length 131.2
  TopLayer w10: v1(3388.39,1176.61) 3388.39,1146.61 3401.73,1133.27 U6_15.37@3435.63,1133.27
  TopLayer w20: v1(3388.39,1176.61) C32_15.1@3388.39,1225
NetC31_16_1: C31_16.1 C32_16.1 U6_16.37 | length 131.2
  TopLayer w10: v1(3388.39,626.61) 3388.39,596.61 3401.73,583.27 U6_16.37@3435.63,583.27
  TopLayer w20: v1(3388.39,626.61) C32_16.1@3388.39,675
NetC34_1_1: C34_1.1 R18_1.2 U4_1.3 | length 282.6
  TopLayer w20: R18_1.2@2587.4,8600 2625,8600 2650,8575 U4_1.3@2747.64,8575
  BottomLayer w20: C34_1.1@2588.39,8600 2625,8600 2650,8575 v1(2690,8575)
NetC34_2_1: C34_2.1 R18_2.2 U4_2.3 | length 282.6
  TopLayer w20: R18_2.2@2587.4,8050 2625,8050 2650,8025 U4_2.3@2747.64,8025
  BottomLayer w20: C34_2.1@2588.39,8050 2625,8050 2650,8025 v1(2690,8025)
NetC34_3_1: C34_3.1 R18_3.2 U4_3.3 | length 282.6
  TopLayer w20: R18_3.2@2587.4,7500 2625,7500 2650,7475 U4_3.3@2747.64,7475
  BottomLayer w20: C34_3.1@2588.39,7500 2625,7500 2650,7475 v1(2690,7475)
NetC34_4_1: C34_4.1 R18_4.2 U4_4.3 | length 282.6
  TopLayer w20: R18_4.2@2587.4,6950 2625,6950 2650,6925 U4_4.3@2747.64,6925
  BottomLayer w20: C34_4.1@2588.39,6950 2625,6950 2650,6925 v1(2690,6925)
NetC34_5_1: C34_5.1 R18_5.2 U4_5.3 | length 282.6
  TopLayer w20: R18_5.2@2587.4,6400 2625,6400 2650,6375 U4_5.3@2747.64,6375
  BottomLayer w20: C34_5.1@2588.39,6400 2625,6400 2650,6375 v1(2690,6375)
NetC34_6_1: C34_6.1 R18_6.2 U4_6.3 | length 282.6
  TopLayer w20: R18_6.2@2587.4,5850 2625,5850 2650,5825 U4_6.3@2747.64,5825
  BottomLayer w20: C34_6.1@2588.39,5850 2625,5850 2650,5825 v1(2690,5825)
NetC34_7_1: C34_7.1 R18_7.2 U4_7.3 | length 282.6
  TopLayer w20: R18_7.2@2587.4,5300 2625,5300 2650,5275 U4_7.3@2747.64,5275
  BottomLayer w20: C34_7.1@2588.39,5300 2625,5300 2650,5275 v1(2690,5275)
NetC34_8_1: C34_8.1 R18_8.2 U4_8.3 | length 282.6
  TopLayer w20: R18_8.2@2587.4,4750 2625,4750 2650,4725 U4_8.3@2747.64,4725
  BottomLayer w20: C34_8.1@2588.39,4750 2625,4750 2650,4725 v1(2690,4725)
NetC34_9_1: C34_9.1 R18_9.2 U4_9.3 | length 282.6
  TopLayer w20: R18_9.2@2587.4,4200 2625,4200 2650,4175 U4_9.3@2747.64,4175
  BottomLayer w20: C34_9.1@2588.39,4200 2625,4200 2650,4175 v1(2690,4175)
NetC34_10_1: C34_10.1 R18_10.2 U4_10.3 | length 282.6
  TopLayer w20: R18_10.2@2587.4,3650 2625,3650 2650,3625 U4_10.3@2747.64,3625
  BottomLayer w20: C34_10.1@2588.39,3650 2625,3650 2650,3625 v1(2690,3625)
NetC34_11_1: C34_11.1 R18_11.2 U4_11.3 | length 282.6
  TopLayer w20: R18_11.2@2587.4,3100 2625,3100 2650,3075 U4_11.3@2747.64,3075
  BottomLayer w20: C34_11.1@2588.39,3100 2625,3100 2650,3075 v1(2690,3075)
NetC34_12_1: C34_12.1 R18_12.2 U4_12.3 | length 282.6
  TopLayer w20: R18_12.2@2587.4,2550 2625,2550 2650,2525 U4_12.3@2747.64,2525
  BottomLayer w20: C34_12.1@2588.39,2550 2625,2550 2650,2525 v1(2690,2525)
NetC34_13_1: C34_13.1 R18_13.2 U4_13.3 | length 282.6
  TopLayer w20: R18_13.2@2587.4,2000 2625,2000 2650,1975 U4_13.3@2747.64,1975
  BottomLayer w20: C34_13.1@2588.39,2000 2625,2000 2650,1975 v1(2690,1975)
NetC34_14_1: C34_14.1 R18_14.2 U4_14.3 | length 282.6
  TopLayer w20: R18_14.2@2587.4,1450 2625,1450 2650,1425 U4_14.3@2747.64,1425
  BottomLayer w20: C34_14.1@2588.39,1450 2625,1450 2650,1425 v1(2690,1425)
NetC34_15_1: C34_15.1 R18_15.2 U4_15.3 | length 282.6
  TopLayer w20: R18_15.2@2587.4,900 2625,900 2650,875 U4_15.3@2747.64,875
  BottomLayer w20: C34_15.1@2588.39,900 2625,900 2650,875 v1(2690,875)
NetC34_16_1: C34_16.1 R18_16.2 U4_16.3 | length 282.6
  TopLayer w20: R18_16.2@2587.4,350 2625,350 2650,325 U4_16.3@2747.64,325
  BottomLayer w20: C34_16.1@2588.39,350 2625,350 2650,325 v1(2690,325)
NetC36_1_1: C36_1.1 R19_1.1 U6_1.39 | length 346.9
  TopLayer w10: R19_1.1@3187.4,8850 3285,8850 3341.1,8793.9 U6_1.39@3435.63,8793.9
  TopLayer w20: R19_1.1@3187.4,8850 3188.39,8850.98 C36_1.1@3188.39,8925
NetC36_2_1: C36_2.1 R19_2.1 U6_2.39 | length 346.9
  TopLayer w10: R19_2.1@3187.4,8300 3285,8300 3341.1,8243.9 U6_2.39@3435.63,8243.9
  TopLayer w20: R19_2.1@3187.4,8300 3188.39,8300.98 C36_2.1@3188.39,8375
NetC36_3_1: C36_3.1 R19_3.1 U6_3.39 | length 346.9
  TopLayer w10: R19_3.1@3187.4,7750 3285,7750 3341.1,7693.9 U6_3.39@3435.63,7693.9
  TopLayer w20: R19_3.1@3187.4,7750 3188.39,7750.98 C36_3.1@3188.39,7825
NetC36_4_1: C36_4.1 R19_4.1 U6_4.39 | length 346.9
  TopLayer w10: R19_4.1@3187.4,7200 3285,7200 3341.1,7143.9 U6_4.39@3435.63,7143.9
  TopLayer w20: R19_4.1@3187.4,7200 3188.39,7200.98 C36_4.1@3188.39,7275
NetC36_5_1: C36_5.1 R19_5.1 U6_5.39 | length 346.9
  TopLayer w10: R19_5.1@3187.4,6650 3285,6650 3341.1,6593.9 U6_5.39@3435.63,6593.9
  TopLayer w20: R19_5.1@3187.4,6650 3188.39,6650.98 C36_5.1@3188.39,6725
NetC36_6_1: C36_6.1 R19_6.1 U6_6.39 | length 346.9
  TopLayer w10: R19_6.1@3187.4,6100 3285,6100 3341.1,6043.9 U6_6.39@3435.63,6043.9
  TopLayer w20: R19_6.1@3187.4,6100 3188.39,6100.98 C36_6.1@3188.39,6175
NetC36_7_1: C36_7.1 R19_7.1 U6_7.39 | length 346.9
  TopLayer w10: R19_7.1@3187.4,5550 3285,5550 3341.1,5493.9 U6_7.39@3435.63,5493.9
  TopLayer w20: R19_7.1@3187.4,5550 3188.39,5550.98 C36_7.1@3188.39,5625
NetC36_8_1: C36_8.1 R19_8.1 U6_8.39 | length 346.9
  TopLayer w10: R19_8.1@3187.4,5000 3285,5000 3341.1,4943.9 U6_8.39@3435.63,4943.9
  TopLayer w20: R19_8.1@3187.4,5000 3188.39,5000.98 C36_8.1@3188.39,5075
NetC36_9_1: C36_9.1 R19_9.1 U6_9.39 | length 346.9
  TopLayer w10: R19_9.1@3187.4,4450 3285,4450 3341.1,4393.9 U6_9.39@3435.63,4393.9
  TopLayer w20: R19_9.1@3187.4,4450 3188.39,4450.98 C36_9.1@3188.39,4525
NetC36_10_1: C36_10.1 R19_10.1 U6_10.39 | length 346.9
  TopLayer w10: R19_10.1@3187.4,3900 3285,3900 3341.1,3843.9 U6_10.39@3435.63,3843.9
  TopLayer w20: R19_10.1@3187.4,3900 3188.39,3900.98 C36_10.1@3188.39,3975
NetC36_11_1: C36_11.1 R19_11.1 U6_11.39 | length 346.9
  TopLayer w10: R19_11.1@3187.4,3350 3285,3350 3341.1,3293.9 U6_11.39@3435.63,3293.9
  TopLayer w20: R19_11.1@3187.4,3350 3188.39,3350.98 C36_11.1@3188.39,3425
NetC36_12_1: C36_12.1 R19_12.1 U6_12.39 | length 346.9
  TopLayer w10: R19_12.1@3187.4,2800 3285,2800 3341.1,2743.9 U6_12.39@3435.63,2743.9
  TopLayer w20: R19_12.1@3187.4,2800 3188.39,2800.98 C36_12.1@3188.39,2875
NetC36_13_1: C36_13.1 R19_13.1 U6_13.39 | length 346.9
  TopLayer w10: R19_13.1@3187.4,2250 3285,2250 3341.1,2193.9 U6_13.39@3435.63,2193.9
  TopLayer w20: R19_13.1@3187.4,2250 3188.39,2250.98 C36_13.1@3188.39,2325
NetC36_14_1: C36_14.1 R19_14.1 U6_14.39 | length 346.9
  TopLayer w10: R19_14.1@3187.4,1700 3285,1700 3341.1,1643.9 U6_14.39@3435.63,1643.9
  TopLayer w20: R19_14.1@3187.4,1700 3188.39,1700.98 C36_14.1@3188.39,1775
NetC36_15_1: C36_15.1 R19_15.1 U6_15.39 | length 346.9
  TopLayer w10: R19_15.1@3187.4,1150 3285,1150 3341.1,1093.9 U6_15.39@3435.63,1093.9
  TopLayer w20: R19_15.1@3187.4,1150 3188.39,1150.98 C36_15.1@3188.39,1225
